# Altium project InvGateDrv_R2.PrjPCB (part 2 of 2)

## Sheet InvGateDriver_4.SchDoc
size A3; SheetNumber: 4; SheetTotal: 7; PageSetup: Record=PageOptions¦CenterHorizontal=True¦CenterVertical=True¦PrintScale=0.69¦XCorrection=1.00¦YCorrection=1.00¦PrintKind=0¦BorderSize=5000000¦LeftOffset=0¦BottomOffset=0¦Orientation=2¦PaperLength=1000¦PaperWidth=1000¦Scale=100¦PaperSource=15¦PrintQuality=600¦MediaType=1¦DitherType=10¦PaperKind=Letter¦PrintScaleMode=1
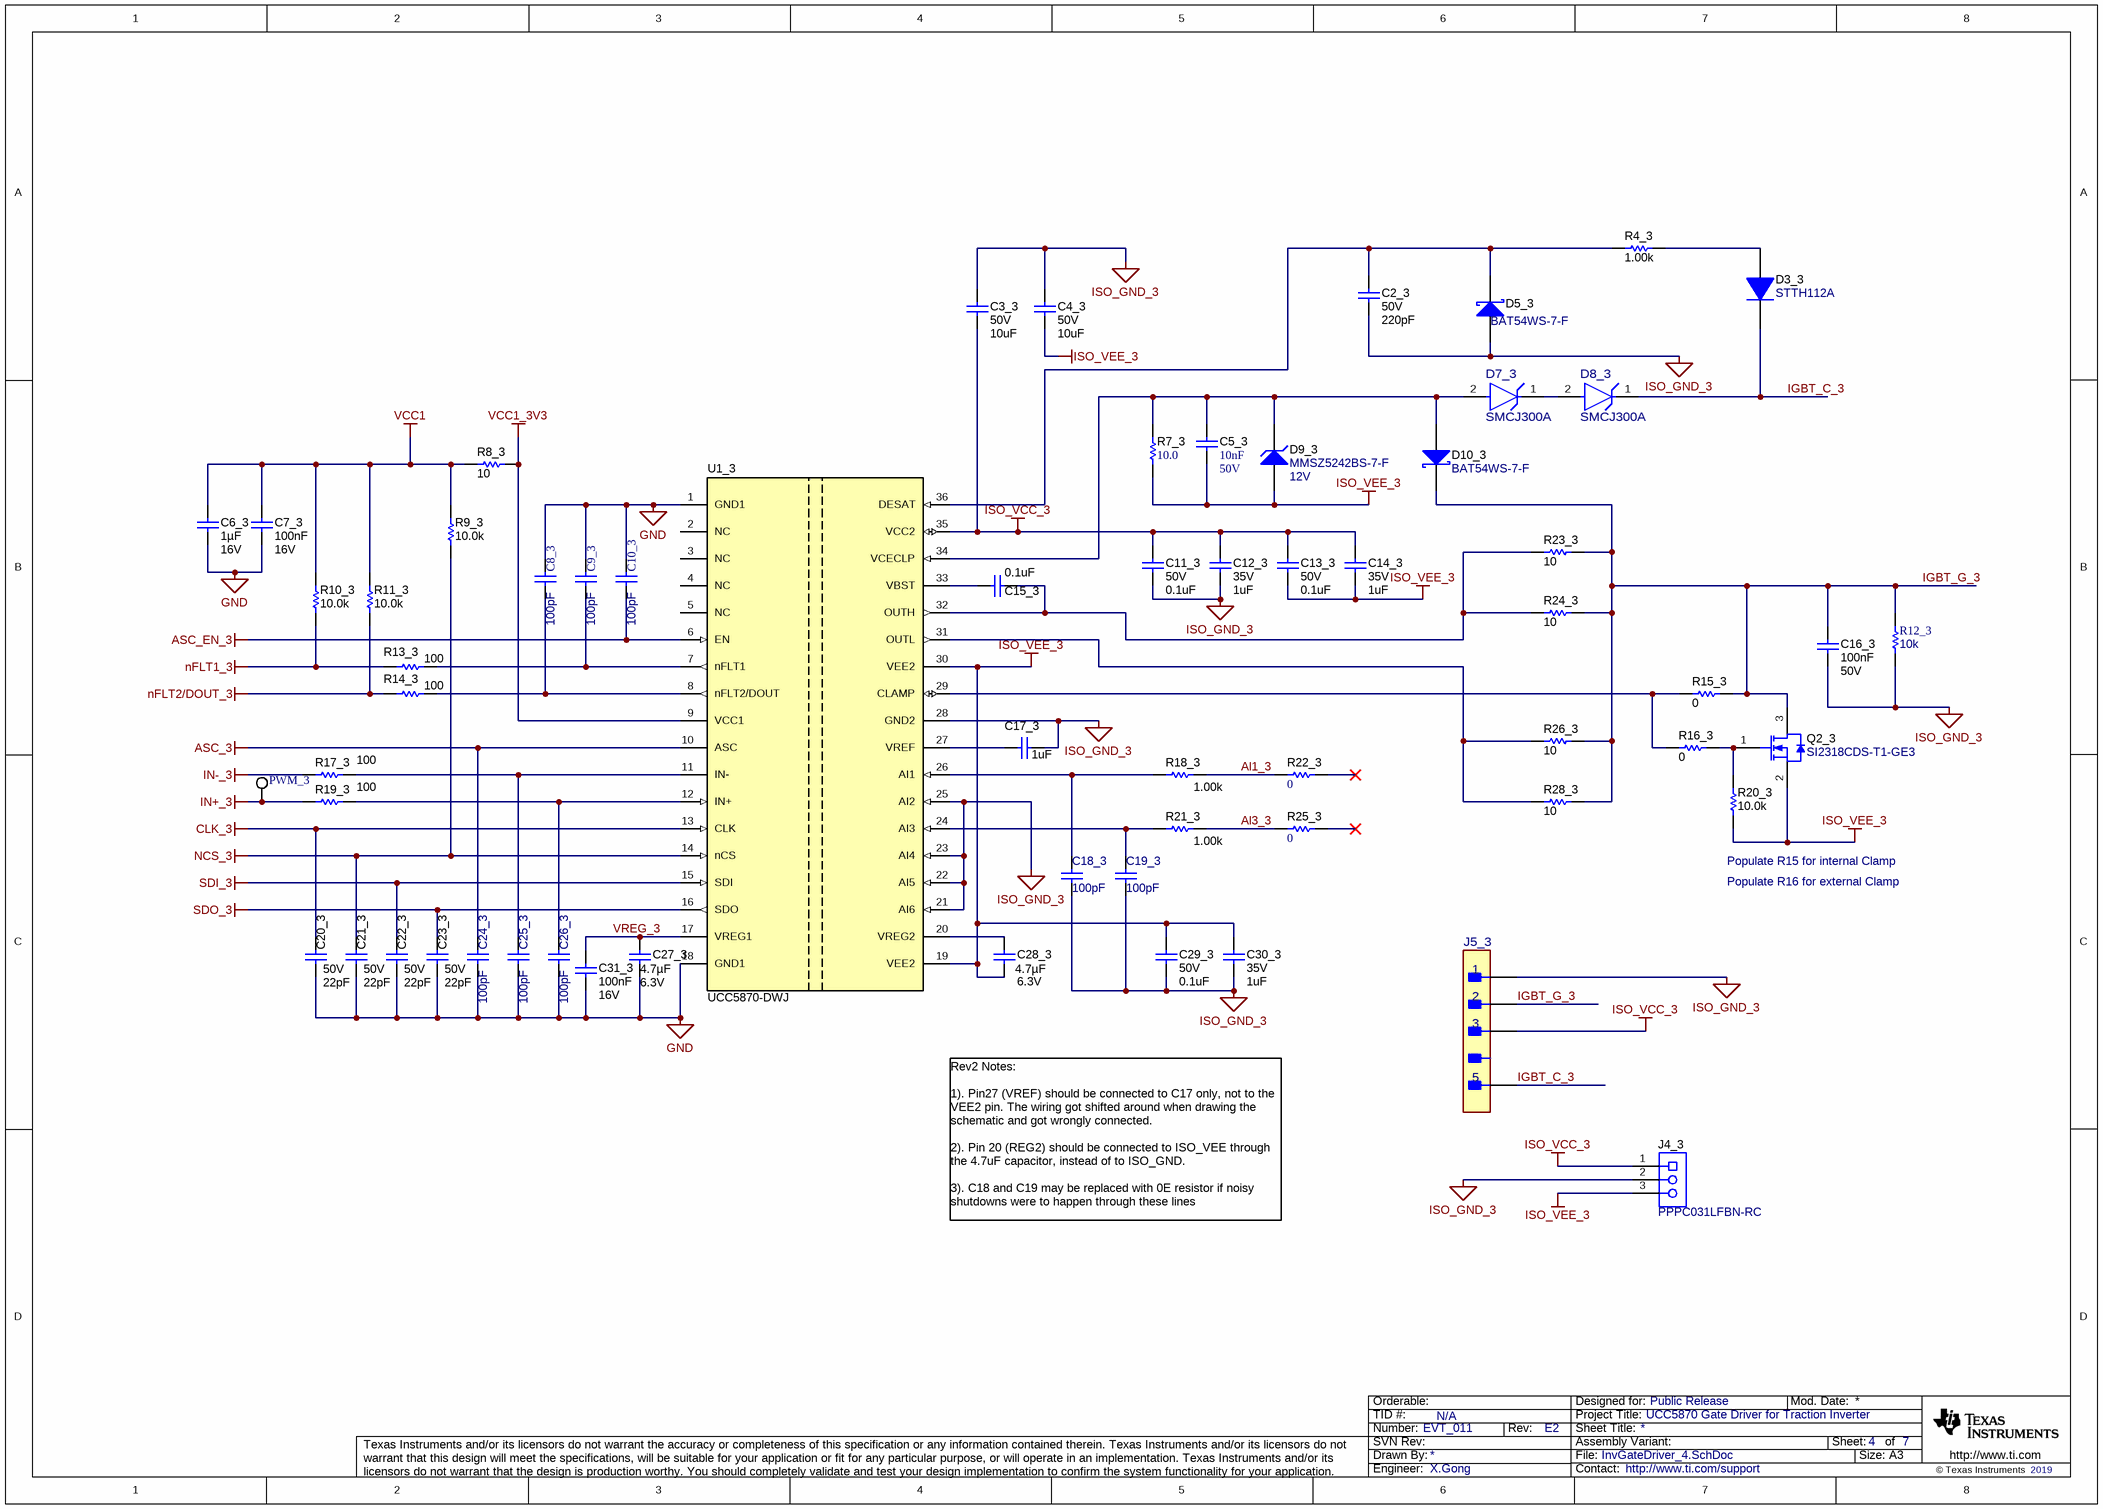
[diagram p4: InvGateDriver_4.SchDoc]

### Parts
C2_3  VDC_V: 50V  ValueDisplayed: 220pF  [0603]  (hidden comment: GRM188R71H221KA01D)
C3_3  VDC_V: 50V  ValueDisplayed: 10uF  [1206_180]  (hidden comment: CL31B106KBHNNNE)
C4_3  VDC_V: 50V  ValueDisplayed: 10uF  [1206_180]  (hidden comment: CL31B106KBHNNNE)
C5_3  Cap_F: 10nF  VDC_V: 50V  [0603]  (hidden comment: GRM188R71H103KA01D)
C6_3  Cap_F: 1µF  VDC_V: 16V  [0603]  (hidden comment: GCM188R71C105MA64D)
C7_3  Cap_F: 100nF  VDC_V: 16V  [0603]  (hidden comment: CGJ3E2X7R1C104K080AA)
C8_3  ValueDisplayed: 100pF  [0603]  (hidden comment: GCM1885C1H101JA16J)
C9_3  ValueDisplayed: 100pF  [0603]  (hidden comment: GCM1885C1H101JA16J)
C10_3  ValueDisplayed: 100pF  [0603]  (hidden comment: GCM1885C1H101JA16J)
C11_3  VDC_V: 50V  ValueDisplayed: 0.1uF  [0603]  (hidden comment: C1608X5R1H104K080AA)
C12_3  VDC_V: 35V  ValueDisplayed: 1uF  [0603]  (hidden comment: CGA3E1X7R1V105K080AC)
C13_3  VDC_V: 50V  ValueDisplayed: 0.1uF  [0603]  (hidden comment: C1608X5R1H104K080AA)
C14_3  VDC_V: 35V  ValueDisplayed: 1uF  [0603]  (hidden comment: CGA3E1X7R1V105K080AC)
C15_3  ValueDisplayed: 0.1uF  [0603]  (hidden comment: C1608X5R1H104K080AA)
C16_3  Cap_F: 100nF  VDC_V: 50V  [0805_HV]  (hidden comment: C0805C104K5RACAUTO)
C17_3  ValueDisplayed: 1uF  [0603]  (hidden comment: CGA3E1X7R1V105K080AC)
C18_3  ValueDisplayed: 100pF  [0603]  (hidden comment: GCM1885C1H101JA16J)
C19_3  ValueDisplayed: 100pF  [0603]  (hidden comment: GCM1885C1H101JA16J)
C20_3  VDC_V: 50V  ValueDisplayed: 22pF  [0603]  (hidden comment: CGA3E2C0G1H220J080AA)
C21_3  VDC_V: 50V  ValueDisplayed: 22pF  [0603]  (hidden comment: CGA3E2C0G1H220J080AA)
C22_3  VDC_V: 50V  ValueDisplayed: 22pF  [0603]  (hidden comment: CGA3E2C0G1H220J080AA)
C23_3  VDC_V: 50V  ValueDisplayed: 22pF  [0603]  (hidden comment: CGA3E2C0G1H220J080AA)
C24_3  ValueDisplayed: 100pF  [0603]  (hidden comment: GCM1885C1H101JA16J)
C25_3  ValueDisplayed: 100pF  [0603]  (hidden comment: GCM1885C1H101JA16J)
C26_3  ValueDisplayed: 100pF  [0603]  (hidden comment: GCM1885C1H101JA16J)
C27_3  Cap_F: 4.7µF  VDC_V: 6.3V  [0603]  (hidden comment: CL10B475KQ8NQND)
C28_3  Cap_F: 4.7µF  VDC_V: 6.3V  [0603]  (hidden comment: CL10B475KQ8NQND)
C29_3  VDC_V: 50V  ValueDisplayed: 0.1uF  [0603]  (hidden comment: C1608X5R1H104K080AA)
C30_3  VDC_V: 35V  ValueDisplayed: 1uF  [0603]  (hidden comment: CGA3E1X7R1V105K080AC)
C31_3  Cap_F: 100nF  VDC_V: 16V  [0603]  (hidden comment: CGJ3E2X7R1C104K080AA)
D3_3  STTH112A  [SMA]
D5_3  BAT54WS-7-F  [SOD-323]
D7_3  SMCJ300A  [FP-SMCJ300A_DO214AB-MFG]
D8_3  SMCJ300A  [FP-SMCJ300A_DO214AB-MFG]
D9_3  MMSZ5242BS-7-F  value 12V  [SOD-323]
D10_3  BAT54WS-7-F  [SOD-323]
J4_3  PPPC031LFBN-RC  [Sullins_PPPC031LFBN-RC]
J5_3  TSW-105-08-G-S-RA-004  [FP-TSW-105-08-G-S-RA-004_HDR4-MFG]  (value not drawn)
PWM_3  5002  [Keystone5002]  (value not drawn)
Q2_3  SI2318CDS-T1-GE3  [SOT-23]
R4_3  ValueDisplayed: 1.00k  [0603]  (hidden comment: CRCW06031K00FKEA)
R7_3  ValueDisplayed: 10.0  [0805_HV]  (hidden comment: CRCW080510R0FKEA)
R8_3  ValueDisplayed: 10  [0805_HV]  (hidden comment: CRCW080510R0JNEA)
R9_3  ValueDisplayed: 10.0k  [0603]  (hidden comment: ERJ-3EKF1002V)
R10_3  ValueDisplayed: 10.0k  [0603]  (hidden comment: ERJ-3EKF1002V)
R11_3  ValueDisplayed: 10.0k  [0603]  (hidden comment: ERJ-3EKF1002V)
R12_3  ValueDisplayed: 10k  [0603]  (hidden comment: CRCW060310K0JNEA)
R13_3  ValueDisplayed: 100  [0603]  (hidden comment: CRCW0603100RJNEA)
R14_3  ValueDisplayed: 100  [0603]  (hidden comment: CRCW0603100RJNEA)
R15_3  ValueDisplayed: 0  [0805_HV]  (hidden comment: CRCW08050000Z0EA)
R16_3  ValueDisplayed: 0  [0805_HV]  (hidden comment: CRCW08050000Z0EA)
R17_3  ValueDisplayed: 100  [0603]  (hidden comment: CRCW0603100RJNEA)
R18_3  ValueDisplayed: 1.00k  [0603]  (hidden comment: CRCW06031K00FKEA)
R19_3  ValueDisplayed: 100  [0603]  (hidden comment: CRCW0603100RJNEA)
R20_3  ValueDisplayed: 10.0k  [0603]  (hidden comment: RCG060310K0FKEA)
R21_3  ValueDisplayed: 1.00k  [0603]  (hidden comment: CRCW06031K00FKEA)
R22_3  ValueDisplayed: 0  [0603]  (hidden comment: CRCW06030000Z0EA)
R23_3  ValueDisplayed: 10  [2010]  (hidden comment: CRCW201010R0JNEF)
R24_3  ValueDisplayed: 10  [2010]  (hidden comment: CRCW201010R0JNEF)
R25_3  ValueDisplayed: 0  [0603]  (hidden comment: CRCW06030000Z0EA)
R26_3  ValueDisplayed: 10  [2010]  (hidden comment: CRCW201010R0JNEF)
R28_3  ValueDisplayed: 10  [2010]  (hidden comment: CRCW201010R0JNEF)
U1_3  UCC5870-DWJ  [DWJ0036A]

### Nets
ASC_3: C24_3.1 U1_3.10(ASC)  [project net ASC_1]
ASC_EN_3: C10_3.2 U1_3.6(EN)  [project net ASC_EN]
CLK_3: C20_3.1 U1_3.13(CLK)  [project net CLK]
GND: C6_3.2 C7_3.2 C8_3.1 C9_3.1 C10_3.1 C20_3.2 C21_3.2 C22_3.2 C23_3.2 C24_3.2 C25_3.2 C26_3.2 C27_3.2 C31_3.2 U1_3.1(GND1) U1_3.18(GND1)
IN+_3: PWM_3.1 R19_3.1  [project net IN+_B]
IN-_3: R17_3.1  [project net IN-_B]
ISO_GND_3: C2_3.1 C3_3.1 C4_3.1 C11_3.2 C12_3.2 C16_3.2 C17_3.2 C18_3.2 C19_3.2 C29_3.2 C30_3.1 D5_3.2(A) J4_3.2 J5_3.1 R12_3.1 U1_3.21(AI6) U1_3.22(AI5) U1_3.23(AI4) U1_3.25(AI2) U1_3.28(GND2)
ISO_VCC_3: C3_3.2 C11_3.1 C12_3.1 C13_3.1 C14_3.1 J4_3.1 J5_3.3 U1_3.35(VCC2)
ISO_VEE_3: C4_3.2 C5_3.2 C13_3.2 C14_3.2 C28_3.2 C29_3.1 C30_3.2 D9_3.2(A) J4_3.3 Q2_3.2(S) R7_3.1 R20_3.1 U1_3.19(VEE2) U1_3.30(VEE2)
NCS_3: C21_3.1 R9_3.1 U1_3.14(nCS)  [project net NCS]
nFLT1_3: R10_3.2 R13_3.1  [project net nFLT1_1]
nFLT2/DOUT_3: R11_3.1 R14_3.1  [project net nFLT2/DOUT_1]
SDI_3: C22_3.1 U1_3.15(SDI)  [project net SDI]
SDO_3: C23_3.1 U1_3.16(SDO)  [project net SDO]
VCC1: C6_3.1 C7_3.1 R8_3.1 R9_3.2 R10_3.1 R11_3.2
VCC1_3V3: R8_3.2 U1_3.9(VCC1)
Al1_3: R18_3.2 R22_3.1
Al3_3: R21_3.2 R25_3.1
IGBT_C_3: D3_3.1(K) D8_3.1(CATHODE) J5_3.5
IGBT_G_3: C16_3.1 D10_3.1(K) J5_3.2 Q2_3.3(D) R12_3.2 R15_3.1 R23_3.2 R24_3.2 R26_3.2 R28_3.2
VREG_3: C27_3.1 C31_3.1 U1_3.17(VREG1)
NetC2_3_2: C2_3.2 D5_3.1(K) R4_3.1 U1_3.36(DESAT)
NetC5_3_1: C5_3.1 D7_3.2(ANODE) D9_3.1(K) D10_3.2(A) R7_3.2 U1_3.34(VCECLP)
NetC8_3_2: C8_3.2 R14_3.2 U1_3.8(nFLT2/DOUT)
NetC9_3_2: C9_3.2 R13_3.2 U1_3.7(nFLT1)
NetC15_3_1: C15_3.1 U1_3.33(VBST)
NetC15_3_2: C15_3.2 R23_3.1 R24_3.1 U1_3.32(OUTH)
NetC17_3_1: C17_3.1 U1_3.27(VREF)
NetC18_3_1: C18_3.1 R18_3.1 U1_3.26(AI1)
NetC19_3_1: C19_3.1 R21_3.1 U1_3.24(AI3)
NetC25_3_1: C25_3.1 R17_3.2 U1_3.11(IN-)
NetC26_3_1: C26_3.1 R19_3.2 U1_3.12(IN+)
NetC28_3_1: C28_3.1 U1_3.20(VREG2)
NetD3_3_2: D3_3.2(A) R4_3.2
NetD7_3_1: D7_3.1(CATHODE) D8_3.2(ANODE)
NetQ2_3_1: Q2_3.1(G) R16_3.1 R20_3.2
NetR15_3_2: R15_3.2 R16_3.2 U1_3.29(CLAMP)
NetR26_3_1: R26_3.1 R28_3.1 U1_3.31(OUTL)

Not connected (* = marked no-connect by the designer): R22_3 2*; R25_3 2*; U1_3 2(NC) 3(NC) 4(NC) 5(NC)

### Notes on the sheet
- (near R20_3) Populate R15 for internal Clamp
- Populate R16 for external Clamp
- Rev2 Notes:
  1). Pin27 (VREF) should be connected to C17 only, not to the VEE2 pin. The wiring got shifted around when drawing the schematic and got wrongly connected.
  2). Pin 20 (REG2) should be connected to ISO_VEE through the 4.7uF capacitor, instead of to ISO_GND.
  3). C18 and C19 may be replaced with 0E resistor if noisy shutdowns were to happen through these lines

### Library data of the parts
C2_3 = CMP-0007442-5: CAP, CERM, 220 pF, 50 V, +/- 10%, X7R, 0603; Manufacturer: MuRata; TaMin_C: -55°C; Polarized: N; SizeAreaWB_mm2: 4.68; Value1: Unknown; U/M: EA; Value: 220pF; TaMax_C: 125°C; SizeZ_mm: 1; SizeX_mm: 1.6; SizeY_mm: 0.8; SizeArea_mm2: 1.28; AEC Category: Q200
C3_3 = CMP-0008802-2: CAP, CERM, 10 uF, 50 V, +/- 10%, X7R, 1206; Manufacturer: Samsung; TaMin_C: -55°C; Polarized: N; SizeAreaWB_mm2: 10.92; Value1: Unknown; U/M: EA; Value: 10uF; TaMax_C: 125°C; SizeZ_mm: 1.8; SizeX_mm: 3.2; SizeY_mm: 1.6; Cap_Case: 1206; SizeArea_mm2: 5.12; Cap_F: 10µF; AEC Category: Q200
C4_3 = CMP-0008802-2: CAP, CERM, 10 uF, 50 V, +/- 10%, X7R, 1206; Manufacturer: Samsung; TaMin_C: -55°C; Polarized: N; SizeAreaWB_mm2: 10.92; Value1: Unknown; U/M: EA; Value: 10uF; TaMax_C: 125°C; SizeZ_mm: 1.8; SizeX_mm: 3.2; SizeY_mm: 1.6; Cap_Case: 1206; SizeArea_mm2: 5.12; CompType: Capacitor; Cap_F: 10µF; AEC Category: Q200
C5_3 = CMP-0007433-4: CAP, CERM, 0.01 uF, 50 V, +/- 10%, X7R, 0603; Manufacturer: MuRata; TaMin_C: -55°C; Polarized: N; SizeAreaWB_mm2: 4.68; Value1: Unknown; U/M: EA; Value: 0.01uF; TaMax_C: 125°C; SizeZ_mm: 1; SizeX_mm: 1.6; SizeY_mm: 0.8; SizeArea_mm2: 1.28; AEC Category: Q200
C6_3 = CMP-0007137-5: CAP, CERM, 1 uF, 16 V, +/- 20%, X7R, AEC-Q200 Grade 1, 0603; Manufacturer: MuRata; TaMin_C: -55°C; Polarized: N; SizeAreaWB_mm2: 4.68; Value1: Unknown; U/M: EA; Value: 1uF; TaMax_C: 125°C; SizeZ_mm: 1; SizeX_mm: 1.6; SizeY_mm: 0.8; SizeArea_mm2: 1.28; AEC Qualified: Y; AEC Category: Q200
C7_3 = CMP-0007106-4: CAP, CERM, 0.1 uF, 16 V, +/- 10%, X7R, AEC-Q200 Grade 1, 0603; Manufacturer: TDK; TaMin_C: -55°C; Polarized: N; SizeAreaWB_mm2: 4.68; Value1: Unknown; U/M: EA; Value: 0.1uF; TaMax_C: 125°C; SizeZ_mm: 1; SizeX_mm: 1.6; SizeY_mm: 0.8; SizeArea_mm2: 1.28; AEC Qualified: Y; AEC Category: Q200
C8_3 C9_3 C10_3 C18_3 C19_3 C24_3 C25_3 C26_3 = CMP-0750041-1: CAP, CERM, 100 pF, 50 V,+/- 5%, C0G/NP0, AEC-Q200 Grade 1, 0603; Manufacturer: MuRata; AEC Grade: 1; SizeArea_mm2: 1.28; SizeX_mm: 1.6; Polarized: N; TaMax_C: 125°C; Value2: 50V; Value: 100pF; U/M: EA; CompType: Capacitor; AEC Qualified: Y; SizeAreaWB_mm2: 4.68; TaMin_C: -55°C; SizeY_mm: 0.8; AEC Category: Q200
C11_3 C29_3 = CMP-0007010-5: CAP, CERM, 0.1 uF, 50 V, +/- 10%, X5R, 0603; Manufacturer: TDK; TaMin_C: -55°C; ESR_ohm: 0.0296; Polarized: N; SizeAreaWB_mm2: 4.68; Value1: 0.0296 ohm; U/M: EA; Value: 0.1uF; TaMax_C: 85°C; SizeZ_mm: 1; SizeX_mm: 1.6; SizeY_mm: 0.8; SizeArea_mm2: 1.28; Cap_F: 100nF; IRMS_A: 9.7199dA; AEC Category: Q200
C12_3 C14_3 C30_3 = CMP-0007067-4: CAP, CERM, 1 uF, 35 V, +/- 10%, X7R, AEC-Q200 Grade 1, 0603; Manufacturer: TDK; TaMin_C: -55°C; ESR_ohm: 5.522m; Polarized: N; SizeAreaWB_mm2: 4.68; Value1: 0.005522 ohm; U/M: EA; Value: 1uF; TaMax_C: 125°C; SizeZ_mm: 1; SizeX_mm: 1.6; SizeY_mm: 0.8; SizeArea_mm2: 1.28; CompType: Capacitor; AEC Qualified: Y; Cap_F: 1µF; IRMS_A: 2.21617A; AEC Category: Q200
C13_3 = CMP-0007010-5: CAP, CERM, 0.1 uF, 50 V, +/- 10%, X5R, 0603; Manufacturer: TDK; TaMin_C: -55°C; ESR_ohm: 0.0296; Polarized: N; SizeAreaWB_mm2: 4.68; Value1: 0.0296 ohm; U/M: EA; Value: 0.1uF; TaMax_C: 85°C; SizeZ_mm: 1; SizeX_mm: 1.6; SizeY_mm: 0.8; SizeArea_mm2: 1.28; CompType: Capacitor; Cap_F: 100nF; IRMS_A: 9.7199dA; AEC Category: Q200
C15_3 = CMP-0007010-5: CAP, CERM, 0.1 uF, 50 V, +/- 10%, X5R, 0603; Manufacturer: TDK; TaMin_C: -55°C; ESR_ohm: 0.0296; Polarized: N; SizeAreaWB_mm2: 4.68; Value1: 0.0296 ohm; U/M: EA; Value: 0.1uF; TaMax_C: 85°C; SizeZ_mm: 1; SizeX_mm: 1.6; SizeY_mm: 0.8; Value2: 50V; SizeArea_mm2: 1.28; CompType: Capacitor; Cap_F: 100nF; IRMS_A: 9.7199dA; AEC Category: Q200
C16_3 = CMP-0007725-2: CAP, CERM, 0.1 uF, 50 V, +/- 10%, X7R, AEC-Q200 Grade 0, 0805; Manufacturer: Kemet; TaMin_C: -55°C; Polarized: N; SizeAreaWB_mm2: 6.75; Value1: Unknown; U/M: EA; Value: 0.1uF; TaMax_C: 125°C; SizeZ_mm: 1.45; SizeX_mm: 2; SizeY_mm: 1.25; Cap_Case: 0805; SizeArea_mm2: 2.5; AEC Qualified: Y; AEC Grade: 0; AEC Category: Q200
C17_3 = CMP-0007067-4: CAP, CERM, 1 uF, 35 V, +/- 10%, X7R, AEC-Q200 Grade 1, 0603; Manufacturer: TDK; TaMin_C: -55°C; ESR_ohm: 5.522m; Polarized: N; SizeAreaWB_mm2: 4.68; Value1: 0.005522 ohm; U/M: EA; Value: 1uF; TaMax_C: 125°C; SizeZ_mm: 1; SizeX_mm: 1.6; SizeY_mm: 0.8; Value2: 35V; SizeArea_mm2: 1.28; CompType: Capacitor; AEC Qualified: Y; Cap_F: 1µF; IRMS_A: 2.21617A; AEC Category: Q200
C20_3 C21_3 C22_3 C23_3 = CMP-0007071-3: CAP, CERM, 22 pF, 50 V, +/- 5%, C0G/NP0, AEC-Q200 Grade 1, 0603; Manufacturer: TDK; TaMin_C: -55°C; Polarized: N; SizeAreaWB_mm2: 4.68; Value1: Unknown; U/M: EA; Value: 22pF; TaMax_C: 125°C; SizeZ_mm: 1; SizeX_mm: 1.6; SizeY_mm: 0.8; SizeArea_mm2: 1.28; AEC Qualified: Y; AEC Category: Q200
C27_3 C28_3 = CMP-0007112-4: CAP, CERM, 4.7 uF, 6.3 V, +/- 10%, X7R, 0603; Manufacturer: Samsung; TaMin_C: -55°C; Polarized: N; SizeAreaWB_mm2: 4.68; Value1: Unknown; U/M: EA; Value: 4.7uF; TaMax_C: 125°C; SizeZ_mm: 1; SizeX_mm: 1.6; SizeY_mm: 0.8; SizeArea_mm2: 1.28; CompType: Capacitor; AEC Category: Q200
C31_3 = CMP-0007106-4: CAP, CERM, 0.1 uF, 16 V, +/- 10%, X7R, AEC-Q200 Grade 1, 0603; Manufacturer: TDK; TaMin_C: -55°C; Polarized: N; SizeAreaWB_mm2: 4.68; Value1: Unknown; U/M: EA; Value: 0.1uF; TaMax_C: 125°C; SizeZ_mm: 1; SizeX_mm: 1.6; SizeY_mm: 0.8; SizeArea_mm2: 1.28; CompType: Capacitor; AEC Qualified: Y; AEC Category: Q200
D3_3 = CMP-0077081-2: Diode, Ultrafast, 1200 V, 1 A, SMA; Manufacturer: STMicroelectronics; SizeAreaWB_mm2: 37.3428; Vr_V: 1.2kV; SizeArea_mm2: 16.3228; AEC Qualified: N; TJmax_C: 175°C; AEC Category: Q101; Value: 1200V; SizeZ_mm: 2.87; Green_REACh: Incomplete; Io_A: 1A; Vf_V: 1.9V; SizeY_mm: 2.92; Green_Lifecycle: Not Set; SizeX_mm: 5.59
D5_3 D10_3 = CMP-0028458-2: Diode, Schottky, 30 V, 0.2 A, SOD-323; Manufacturer: Diodes Inc.; Io_A: 200mA; Green_Lifecycle: Active; SizeAreaWB_mm2: 8.695; Vr_V: 30V; Green_REACh: Passed; Value1: 0.2A; TJmax_C: 125°C; Value: 30V; SizeZ_mm: 1; SizeX_mm: 2.7; SizeY_mm: 1.35; Vf_V: 700mV; Value2: 0.7V; SizeArea_mm2: 3.645; AEC Category: Q101
D7_3 D8_3 = CMP-0088475-1: 486V Clamp 3.1A Ipp Tvs Diode Surface Mount DO-214AB (SMCJ); Manufacturer: Littelfuse Inc; Ppk: 1.5kW; VRWM: 300V; AEC Qualified: No; TJmax_C: +150°C; Number Of Channels: 1; Direction: Unidirectional; SizeZ_mm: 2.62mm; Breakdown Voltage: 335V
D9_3 = CMP-0005831-4: Diode, Zener, 12 V, 200 mW, SOD-323; Manufacturer: Diodes Inc.; Power_W: 200mW; SizeAreaWB_mm2: 8.695; Value1: 0.2W; RJA_CperW: 350; SizeZ_mm: 1; SizeX_mm: 2.7; SizeY_mm: 1.35; SizeArea_mm2: 3.645; AEC Category: Q101
J4_3 = CMP-0054646-1: Receptacle, 100mil, 3x1, Gold, TH; Manufacturer: Sullins Connector Solutions; CT: TRUE; CompType: Socket Strip; CNHeader: FALSE
J5_3 = CMP-0088430-1: THROUGH-HOLE .025" SQ POST HEADER; Manufacturer: Samtec; SizeZ_mm: 3.15mm; Row_Count: 1; Voltage_V: 550V; ContactFinish: Gold,Nickel; Conn Orientation: Right Angle; Conn Gender: Male; AEC Qualified: No; DUT-Pitch_mm: 2.54mm
PWM_3 = CMP-0055139-1: Test Point, Miniature, White, TH; Manufacturer: Keystone; ContactFinish: Silver; Green_Lifecycle: Active; Green_REACh: Passed; CNHeader: FALSE; CT: TRUE
Q2_3 = CMP-0000739-1: MOSFET, N-CH, 40 V, 5.6 A, SOT-23; Alternate Manufacturer: None; Manufacturer: Vishay-Siliconix; SizeZ_mm: 1.1; ChType: N; Value2: 5.8 nC; Value1: 0.05; VdsMax_V: 40V; SizeX_mm: 2.5; SizeY_mm: 3; Vgs_V: 20V; Value: 40V; Rdson45_ohm: 0.051; SizeArea_mm2: 7.5; AEC Category: Q101; IdsMax_A: 5.6A; SizeAreaWB_mm2: 14; U/M: EA; QgTyp_nC: 5.8
R4_3 R18_3 R21_3 = CMP-0022109-5: RES, 1.00 k, 1%, 0.1 W, AEC-Q200 Grade 0, 0603; Manufacturer: Vishay-Dale; Power_W: 100mW; TempCo: 100 ppm/C; Value_Code: 1k00; Value: 1.00k; EIA_Code: E96; Res_ohm: 1k; SizeX_mm: 1.6; SizeY_mm: 0.8; SizeZ_mm: 1; Value2: 0.1W; SizeArea_mm2: 1.28; AEC Qualified: Y; VDC_V: 75V; AEC Category: Q200; AEC Grade: 0
R7_3 = CMP-0020847-3: RES, 10.0, 1%, 0.125 W, AEC-Q200 Grade 0, 0805; Manufacturer: Vishay-Dale; Power_W: 125mW; TempCo: 100 ppm/C; Value_Code: 10R0; Value: 10.0; EIA_Code: E96; Res_ohm: 10; SizeX_mm: 2; SizeY_mm: 1.25; SizeZ_mm: 1.45; Value2: 0.125W; SizeArea_mm2: 2.5; AEC Qualified: Y; VDC_V: 150V; AEC Category: Q200; AEC Grade: 0
R8_3 = CRCW080510R0JNEA: RES, 10, 5%, 0.125 W, 0805; Manufacturer: Vishay-Dale; CompType: Resistor; Value: 10; Value_Code: 10R0; Tolerance_%: 5; Power_W: 0.125; Value2: 0.125W; VDC_V: 150; TempCo: 200 ppm/C; SizeArea_mm2: 2.5; SizeX_mm: 2; SizeY_mm: 1.25; SizeZ_mm: 1.45; EIA_Code: E24; U/M: EA; AEC Category: Q200; Green_Lifecycle: Active; Green_REACh: Passed
R9_3 R10_3 R11_3 = CMP-0022684-3: RES, 10.0 k, 1%, 0.1 W, 0603; Manufacturer: Panasonic; Power_W: 100mW; TempCo: 100 ppm/C; Value_Code: 10k0; U/M: EA; Value: 10.0k; EIA_Code: E96; Res_ohm: 10k; SizeX_mm: 1.6; SizeY_mm: 0.8; SizeZ_mm: 1; Value2: 0.1W; SizeArea_mm2: 1.28; VDC_V: 75V; AEC Category: Q200
R12_3 = CMP-0025701-4: RES, 10 k, 5%, 0.1 W, AEC-Q200 Grade 0, 0603; Manufacturer: Vishay-Dale; Power_W: 100mW; TempCo: 200 ppm/C; Value_Code: 10k0; Value: 10k; EIA_Code: E24; SizeX_mm: 1.6; SizeY_mm: 0.8; SizeZ_mm: 1; Value2: 0.1W; SizeArea_mm2: 1.28; AEC Qualified: Y; VDC_V: 75V; AEC Category: Q200; AEC Grade: 0
R13_3 R14_3 R17_3 R19_3 = CMP-0025700-4: RES, 100, 5%, 0.1 W, AEC-Q200 Grade 0, 0603; Manufacturer: Vishay-Dale; Power_W: 100mW; TempCo: 200 ppm/C; Value_Code: 100R; Value: 100; EIA_Code: E24; SizeX_mm: 1.6; SizeY_mm: 0.8; SizeZ_mm: 1; Value2: 0.1W; SizeArea_mm2: 1.28; AEC Qualified: Y; VDC_V: 75V; AEC Category: Q200; AEC Grade: 0
R15_3 R16_3 = CRCW08050000Z0EA: RES, 0, 5%, 0.125 W, 0805; Manufacturer: Vishay-Dale; CompType: Resistor; Value: 0; Value_Code: 0000; Tolerance_%: 5; Power_W: 0.125; Value2: 0.125W; VDC_V: 150; TempCo: 200 ppm/C; SizeArea_mm2: 2.5; SizeX_mm: 2; SizeY_mm: 1.25; SizeZ_mm: 1.45; EIA_Code: E24; U/M: EA; AEC Category: Q200; Green_Lifecycle: Active; Green_REACh: Passed
R20_3 = RCG060310K0FKEA: RES, 10.0 k, 1%, 0.1 W, 0603; Manufacturer: Vishay Draloric; CompType: Resistor; Value: 10.0k; Res_ohm: 10000; Value_Code: 10k0; Tolerance_%: 1; Power_W: 0.1; Value2: 0.1W; VDC_V: 75; TempCo: 100 ppm/C; SizeArea_mm2: 1.28; SizeX_mm: 1.6; SizeY_mm: 0.8; EIA_Code: E96; U/M: EA; AEC Category: Q200; AEC Qualified: N
R22_3 R25_3 = CMP-0025697-4: RES, 0, 5%, 0.1 W, AEC-Q200 Grade 0, 0603; Manufacturer: Vishay-Dale; Power_W: 100mW; TempCo: 200 ppm/C; Value_Code: 0000; Value: 0; EIA_Code: E24; SizeX_mm: 1.6; SizeY_mm: 0.8; SizeZ_mm: 1; Value2: 0.1W; SizeArea_mm2: 1.28; AEC Qualified: Y; VDC_V: 75V; AEC Category: Q200
R23_3 R24_3 R26_3 R28_3 = CRCW201010R0JNEF: RES, 10, 5%, 0.75 W, AEC-Q200 Grade 0, 2010; Manufacturer: Vishay-Dale; CompType: Resistor; Value: 10; Value_Code: 10R0; Tolerance_%: 5; Power_W: 0.75; Value2: 0.75W; VDC_V: 400; TempCo: 200 ppm/C; SizeArea_mm2: 12.5; SizeY_mm: 2.5; SizeZ_mm: 1.66; EIA_Code: E24; U/M: EA; AEC Category: Q200; AEC Qualified: Y; AEC Grade: 0
U1_3 = CMP-0080759-3: Isolated IGBT, SiC MOSFET Gate Driver With Real-Time Programmability, DWJ0036A (SOIC-36); Alternate Manufacturer: Texas Instruments; SizeAreaWB_mm2: 182.04; SizeZ_mm: 3.55; SizeX_mm: 10.3; SizeY_mm: 12.8; SizeArea_mm2: 131.84; CompType: IC; AEC Qualified: N; AEC Category: Q200

## Sheet InvGateDriver_5.SchDoc
size A3; SheetNumber: 5; SheetTotal: 7; PageSetup: Record=PageOptions¦CenterHorizontal=True¦CenterVertical=True¦PrintScale=0.69¦XCorrection=1.00¦YCorrection=1.00¦PrintKind=0¦BorderSize=5000000¦LeftOffset=0¦BottomOffset=0¦Orientation=2¦PaperLength=1000¦PaperWidth=1000¦Scale=100¦PaperSource=15¦PrintQuality=600¦MediaType=1¦DitherType=10¦PaperKind=Letter¦PrintScaleMode=1
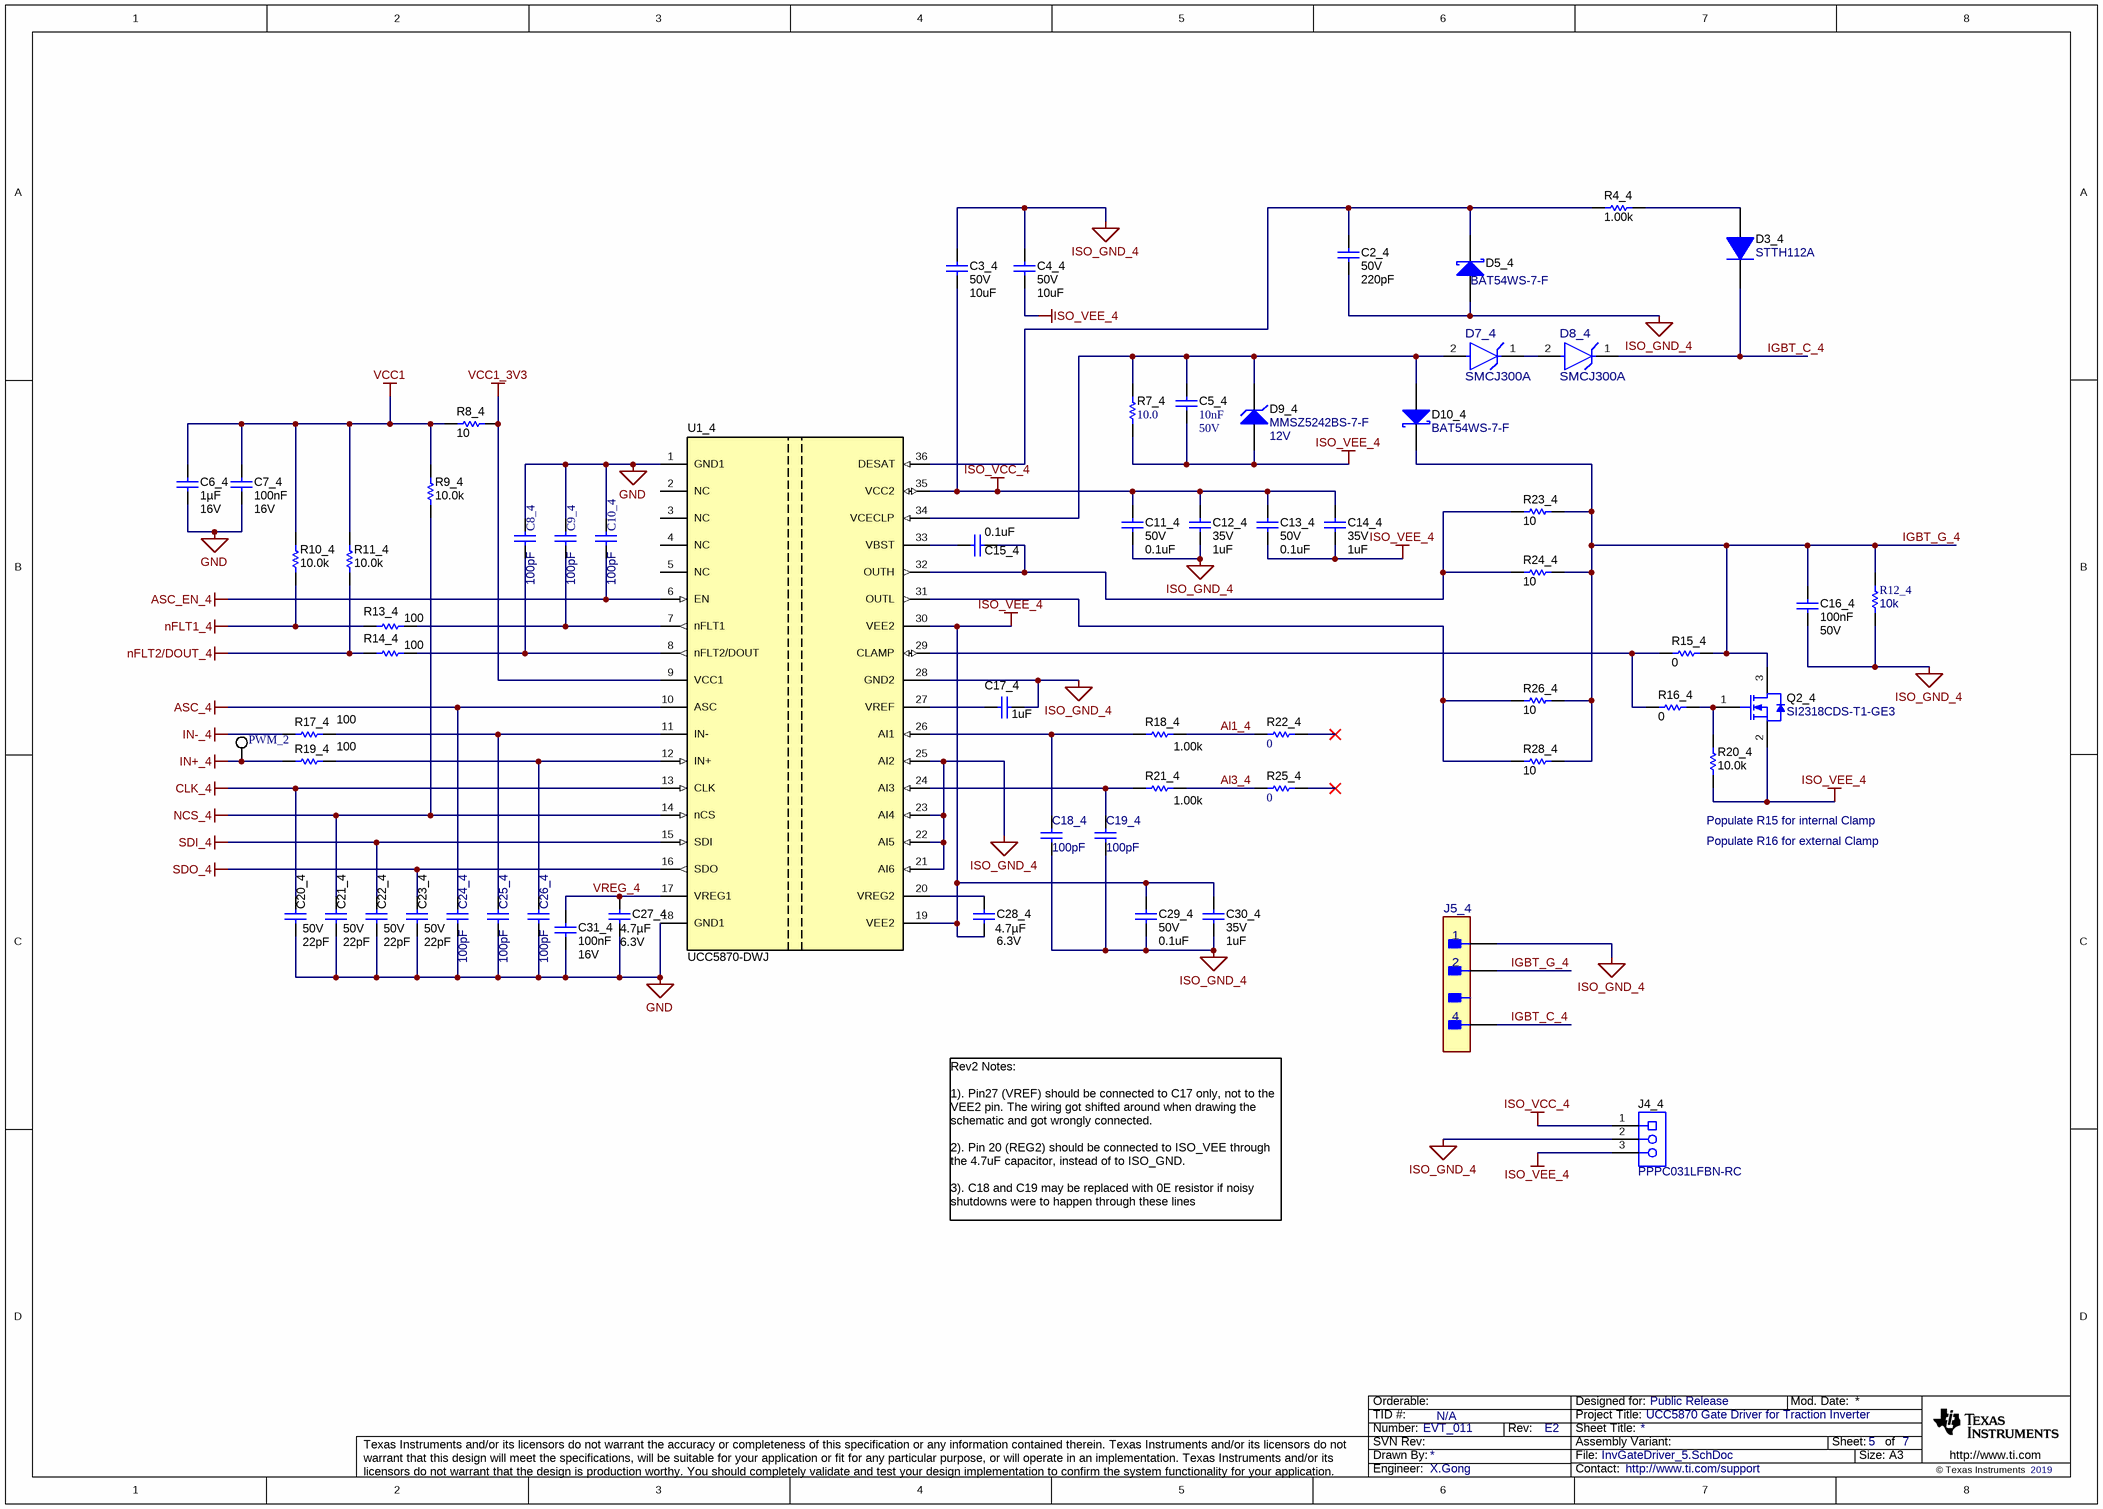
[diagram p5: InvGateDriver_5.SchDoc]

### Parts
C2_4  VDC_V: 50V  ValueDisplayed: 220pF  [0603]  (hidden comment: GRM188R71H221KA01D)
C3_4  VDC_V: 50V  ValueDisplayed: 10uF  [1206_180]  (hidden comment: CL31B106KBHNNNE)
C4_4  VDC_V: 50V  ValueDisplayed: 10uF  [1206_180]  (hidden comment: CL31B106KBHNNNE)
C5_4  Cap_F: 10nF  VDC_V: 50V  [0603]  (hidden comment: GRM188R71H103KA01D)
C6_4  Cap_F: 1µF  VDC_V: 16V  [0603]  (hidden comment: GCM188R71C105MA64D)
C7_4  Cap_F: 100nF  VDC_V: 16V  [0603]  (hidden comment: CGJ3E2X7R1C104K080AA)
C8_4  ValueDisplayed: 100pF  [0603]  (hidden comment: GCM1885C1H101JA16J)
C9_4  ValueDisplayed: 100pF  [0603]  (hidden comment: GCM1885C1H101JA16J)
C10_4  ValueDisplayed: 100pF  [0603]  (hidden comment: GCM1885C1H101JA16J)
C11_4  VDC_V: 50V  ValueDisplayed: 0.1uF  [0603]  (hidden comment: C1608X5R1H104K080AA)
C12_4  VDC_V: 35V  ValueDisplayed: 1uF  [0603]  (hidden comment: CGA3E1X7R1V105K080AC)
C13_4  VDC_V: 50V  ValueDisplayed: 0.1uF  [0603]  (hidden comment: C1608X5R1H104K080AA)
C14_4  VDC_V: 35V  ValueDisplayed: 1uF  [0603]  (hidden comment: CGA3E1X7R1V105K080AC)
C15_4  ValueDisplayed: 0.1uF  [0603]  (hidden comment: C1608X5R1H104K080AA)
C16_4  Cap_F: 100nF  VDC_V: 50V  [0805_HV]  (hidden comment: C0805C104K5RACAUTO)
C17_4  ValueDisplayed: 1uF  [0603]  (hidden comment: CGA3E1X7R1V105K080AC)
C18_4  ValueDisplayed: 100pF  [0603]  (hidden comment: GCM1885C1H101JA16J)
C19_4  ValueDisplayed: 100pF  [0603]  (hidden comment: GCM1885C1H101JA16J)
C20_4  VDC_V: 50V  ValueDisplayed: 22pF  [0603]  (hidden comment: CGA3E2C0G1H220J080AA)
C21_4  VDC_V: 50V  ValueDisplayed: 22pF  [0603]  (hidden comment: CGA3E2C0G1H220J080AA)
C22_4  VDC_V: 50V  ValueDisplayed: 22pF  [0603]  (hidden comment: CGA3E2C0G1H220J080AA)
C23_4  VDC_V: 50V  ValueDisplayed: 22pF  [0603]  (hidden comment: CGA3E2C0G1H220J080AA)
C24_4  ValueDisplayed: 100pF  [0603]  (hidden comment: GCM1885C1H101JA16J)
C25_4  ValueDisplayed: 100pF  [0603]  (hidden comment: GCM1885C1H101JA16J)
C26_4  ValueDisplayed: 100pF  [0603]  (hidden comment: GCM1885C1H101JA16J)
C27_4  Cap_F: 4.7µF  VDC_V: 6.3V  [0603]  (hidden comment: CL10B475KQ8NQND)
C28_4  Cap_F: 4.7µF  VDC_V: 6.3V  [0603]  (hidden comment: CL10B475KQ8NQND)
C29_4  VDC_V: 50V  ValueDisplayed: 0.1uF  [0603]  (hidden comment: C1608X5R1H104K080AA)
C30_4  VDC_V: 35V  ValueDisplayed: 1uF  [0603]  (hidden comment: CGA3E1X7R1V105K080AC)
C31_4  Cap_F: 100nF  VDC_V: 16V  [0603]  (hidden comment: CGJ3E2X7R1C104K080AA)
D3_4  STTH112A  [SMA]
D5_4  BAT54WS-7-F  [SOD-323]
D7_4  SMCJ300A  [FP-SMCJ300A_DO214AB-MFG]
D8_4  SMCJ300A  [FP-SMCJ300A_DO214AB-MFG]
D9_4  MMSZ5242BS-7-F  value 12V  [SOD-323]
D10_4  BAT54WS-7-F  [SOD-323]
J4_4  PPPC031LFBN-RC  [Sullins_PPPC031LFBN-RC]
J5_4  TSW-104-08-G-S-RA-003  [FP-TSW-104-08-G-S-RA-003_HDR3-MFG]  (value not drawn)
PWM_2  5002  [Keystone5002]  (value not drawn)
Q2_4  SI2318CDS-T1-GE3  [SOT-23]
R4_4  ValueDisplayed: 1.00k  [0603]  (hidden comment: CRCW06031K00FKEA)
R7_4  ValueDisplayed: 10.0  [0805_HV]  (hidden comment: CRCW080510R0FKEA)
R8_4  ValueDisplayed: 10  [0805_HV]  (hidden comment: CRCW080510R0JNEA)
R9_4  ValueDisplayed: 10.0k  [0603]  (hidden comment: ERJ-3EKF1002V)
R10_4  ValueDisplayed: 10.0k  [0603]  (hidden comment: ERJ-3EKF1002V)
R11_4  ValueDisplayed: 10.0k  [0603]  (hidden comment: ERJ-3EKF1002V)
R12_4  ValueDisplayed: 10k  [0603]  (hidden comment: CRCW060310K0JNEA)
R13_4  ValueDisplayed: 100  [0603]  (hidden comment: CRCW0603100RJNEA)
R14_4  ValueDisplayed: 100  [0603]  (hidden comment: CRCW0603100RJNEA)
R15_4  ValueDisplayed: 0  [0805_HV]  (hidden comment: CRCW08050000Z0EA)
R16_4  ValueDisplayed: 0  [0805_HV]  (hidden comment: CRCW08050000Z0EA)
R17_4  ValueDisplayed: 100  [0603]  (hidden comment: CRCW0603100RJNEA)
R18_4  ValueDisplayed: 1.00k  [0603]  (hidden comment: CRCW06031K00FKEA)
R19_4  ValueDisplayed: 100  [0603]  (hidden comment: CRCW0603100RJNEA)
R20_4  ValueDisplayed: 10.0k  [0603]  (hidden comment: RCG060310K0FKEA)
R21_4  ValueDisplayed: 1.00k  [0603]  (hidden comment: CRCW06031K00FKEA)
R22_4  ValueDisplayed: 0  [0603]  (hidden comment: CRCW06030000Z0EA)
R23_4  ValueDisplayed: 10  [2010]  (hidden comment: CRCW201010R0JNEF)
R24_4  ValueDisplayed: 10  [2010]  (hidden comment: CRCW201010R0JNEF)
R25_4  ValueDisplayed: 0  [0603]  (hidden comment: CRCW06030000Z0EA)
R26_4  ValueDisplayed: 10  [2010]  (hidden comment: CRCW201010R0JNEF)
R28_4  ValueDisplayed: 10  [2010]  (hidden comment: CRCW201010R0JNEF)
U1_4  UCC5870-DWJ  [DWJ0036A]

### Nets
ASC_4: C24_4.1 U1_4.10(ASC)  [project net ASC]
ASC_EN_4: C10_4.2 U1_4.6(EN)  [project net ASC_EN]
CLK_4: C20_4.1 U1_4.13(CLK)  [project net CLK]
GND: C6_4.2 C7_4.2 C8_4.1 C9_4.1 C10_4.1 C20_4.2 C21_4.2 C22_4.2 C23_4.2 C24_4.2 C25_4.2 C26_4.2 C27_4.2 C31_4.2 U1_4.1(GND1) U1_4.18(GND1)
IN+_4: PWM_2.1 R19_4.1  [project net IN-_A]
IN-_4: R17_4.1  [project net IN+_A]
ISO_GND_4: C2_4.1 C3_4.1 C4_4.1 C11_4.2 C12_4.2 C16_4.2 C17_4.2 C18_4.2 C19_4.2 C29_4.2 C30_4.1 D5_4.2(A) J4_4.2 J5_4.1 R12_4.1 U1_4.21(AI6) U1_4.22(AI5) U1_4.23(AI4) U1_4.25(AI2) U1_4.28(GND2)
ISO_VCC_4: C3_4.2 C11_4.1 C12_4.1 C13_4.1 C14_4.1 J4_4.1 U1_4.35(VCC2)
ISO_VEE_4: C4_4.2 C5_4.2 C13_4.2 C14_4.2 C28_4.2 C29_4.1 C30_4.2 D9_4.2(A) J4_4.3 Q2_4.2(S) R7_4.1 R20_4.1 U1_4.19(VEE2) U1_4.30(VEE2)
NCS_4: C21_4.1 R9_4.1 U1_4.14(nCS)  [project net NCS]
nFLT1_4: R10_4.2 R13_4.1  [project net nFLT1]
nFLT2/DOUT_4: R11_4.1 R14_4.1  [project net nFLT2/DOUT]
SDI_4: C22_4.1 U1_4.15(SDI)  [project net SDI]
SDO_4: C23_4.1 U1_4.16(SDO)  [project net SDO]
VCC1: C6_4.1 C7_4.1 R8_4.1 R9_4.2 R10_4.1 R11_4.2
VCC1_3V3: R8_4.2 U1_4.9(VCC1)
Al1_4: R18_4.2 R22_4.1
Al3_4: R21_4.2 R25_4.1
IGBT_C_4: D3_4.1(K) D8_4.1(CATHODE) J5_4.4
IGBT_G_4: C16_4.1 D10_4.1(K) J5_4.2 Q2_4.3(D) R12_4.2 R15_4.1 R23_4.2 R24_4.2 R26_4.2 R28_4.2
VREG_4: C27_4.1 C31_4.1 U1_4.17(VREG1)
NetC2_4_2: C2_4.2 D5_4.1(K) R4_4.1 U1_4.36(DESAT)
NetC5_4_1: C5_4.1 D7_4.2(ANODE) D9_4.1(K) D10_4.2(A) R7_4.2 U1_4.34(VCECLP)
NetC8_4_2: C8_4.2 R14_4.2 U1_4.8(nFLT2/DOUT)
NetC9_4_2: C9_4.2 R13_4.2 U1_4.7(nFLT1)
NetC15_4_1: C15_4.1 U1_4.33(VBST)
NetC15_4_2: C15_4.2 R23_4.1 R24_4.1 U1_4.32(OUTH)
NetC17_4_1: C17_4.1 U1_4.27(VREF)
NetC18_4_1: C18_4.1 R18_4.1 U1_4.26(AI1)
NetC19_4_1: C19_4.1 R21_4.1 U1_4.24(AI3)
NetC25_4_1: C25_4.1 R17_4.2 U1_4.11(IN-)
NetC26_4_1: C26_4.1 R19_4.2 U1_4.12(IN+)
NetC28_4_1: C28_4.1 U1_4.20(VREG2)
NetD3_4_2: D3_4.2(A) R4_4.2
NetD7_4_1: D7_4.1(CATHODE) D8_4.2(ANODE)
NetQ2_4_1: Q2_4.1(G) R16_4.1 R20_4.2
NetR15_4_2: R15_4.2 R16_4.2 U1_4.29(CLAMP)
NetR26_4_1: R26_4.1 R28_4.1 U1_4.31(OUTL)

Not connected (* = marked no-connect by the designer): R22_4 2*; R25_4 2*; U1_4 2(NC) 3(NC) 4(NC) 5(NC)

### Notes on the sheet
- (near R20_4) Populate R15 for internal Clamp
- Populate R16 for external Clamp
- Rev2 Notes:
  1). Pin27 (VREF) should be connected to C17 only, not to the VEE2 pin. The wiring got shifted around when drawing the schematic and got wrongly connected.
  2). Pin 20 (REG2) should be connected to ISO_VEE through the 4.7uF capacitor, instead of to ISO_GND.
  3). C18 and C19 may be replaced with 0E resistor if noisy shutdowns were to happen through these lines

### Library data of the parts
C2_4 = CMP-0007442-5: as C2_3 on sheet InvGateDriver_4
C3_4 = CMP-0008802-2: as C3_3 on sheet InvGateDriver_4
C4_4 = CMP-0008802-2: as C4_3 on sheet InvGateDriver_4
C5_4 = CMP-0007433-4: as C5_3 on sheet InvGateDriver_4
C6_4 = CMP-0007137-5: as C6_3 on sheet InvGateDriver_4
C7_4 = CMP-0007106-4: as C7_3 on sheet InvGateDriver_4
C8_4 C9_4 C10_4 C18_4 C19_4 C24_4 C25_4 C26_4 = CMP-0750041-1: as C8_3 on sheet InvGateDriver_4
C11_4 C29_4 = CMP-0007010-5: as C11_3 on sheet InvGateDriver_4
C12_4 C14_4 C30_4 = CMP-0007067-4: as C12_3 on sheet InvGateDriver_4
C13_4 = CMP-0007010-5: as C13_3 on sheet InvGateDriver_4
C15_4 = CMP-0007010-5: as C15_3 on sheet InvGateDriver_4
C16_4 = CMP-0007725-2: as C16_3 on sheet InvGateDriver_4
C17_4 = CMP-0007067-4: as C17_3 on sheet InvGateDriver_4
C20_4 C21_4 C22_4 C23_4 = CMP-0007071-3: as C20_3 on sheet InvGateDriver_4
C27_4 C28_4 = CMP-0007112-4: as C27_3 on sheet InvGateDriver_4
C31_4 = CMP-0007106-4: as C31_3 on sheet InvGateDriver_4
D3_4 = CMP-0077081-2: as D3_3 on sheet InvGateDriver_4
D5_4 D10_4 = CMP-0028458-2: as D5_3 on sheet InvGateDriver_4
D7_4 D8_4 = CMP-0088475-1: as D7_3 on sheet InvGateDriver_4
D9_4 = CMP-0005831-4: as D9_3 on sheet InvGateDriver_4
J4_4 = CMP-0054646-1: as J4_3 on sheet InvGateDriver_4
J5_4 = CMP-0088429-1: Conn Unshrouded Header HDR 4 POS 2.54mm Solder RA Thru-Hole Automotive Bulk; Manufacturer: Samtec; Conn Orientation: Right Angle; SizeZ_mm: 3.15mm; Voltage_V: 550V; Row_Count: 1; AEC Qualified: No; ContactFinish: Gold,Nickel; Conn Gender: Male
PWM_2 = CMP-0055139-1: as PWM_3 on sheet InvGateDriver_4
Q2_4 = CMP-0000739-1: as Q2_3 on sheet InvGateDriver_4
R4_4 R18_4 R21_4 = CMP-0022109-5: as R4_3 on sheet InvGateDriver_4
R7_4 = CMP-0020847-3: as R7_3 on sheet InvGateDriver_4
R8_4 = CRCW080510R0JNEA: as R8_3 on sheet InvGateDriver_4
R9_4 R10_4 R11_4 = CMP-0022684-3: as R9_3 on sheet InvGateDriver_4
R12_4 = CMP-0025701-4: as R12_3 on sheet InvGateDriver_4
R13_4 R14_4 R17_4 R19_4 = CMP-0025700-4: as R13_3 on sheet InvGateDriver_4
R15_4 R16_4 = CRCW08050000Z0EA: as R15_3 on sheet InvGateDriver_4
R20_4 = RCG060310K0FKEA: as R20_3 on sheet InvGateDriver_4
R22_4 R25_4 = CMP-0025697-4: as R22_3 on sheet InvGateDriver_4
R23_4 R24_4 R26_4 R28_4 = CRCW201010R0JNEF: as R23_3 on sheet InvGateDriver_4
U1_4 = CMP-0080759-3: as U1_3 on sheet InvGateDriver_4

## Sheet InvGateDriver_6.SchDoc
size A3; SheetNumber: 6; SheetTotal: 7; PageSetup: Record=PageOptions¦CenterHorizontal=True¦CenterVertical=True¦PrintScale=0.69¦XCorrection=1.00¦YCorrection=1.00¦PrintKind=0¦BorderSize=5000000¦LeftOffset=0¦BottomOffset=0¦Orientation=2¦PaperLength=1000¦PaperWidth=1000¦Scale=100¦PaperSource=15¦PrintQuality=600¦MediaType=1¦DitherType=10¦PaperKind=Letter¦PrintScaleMode=1
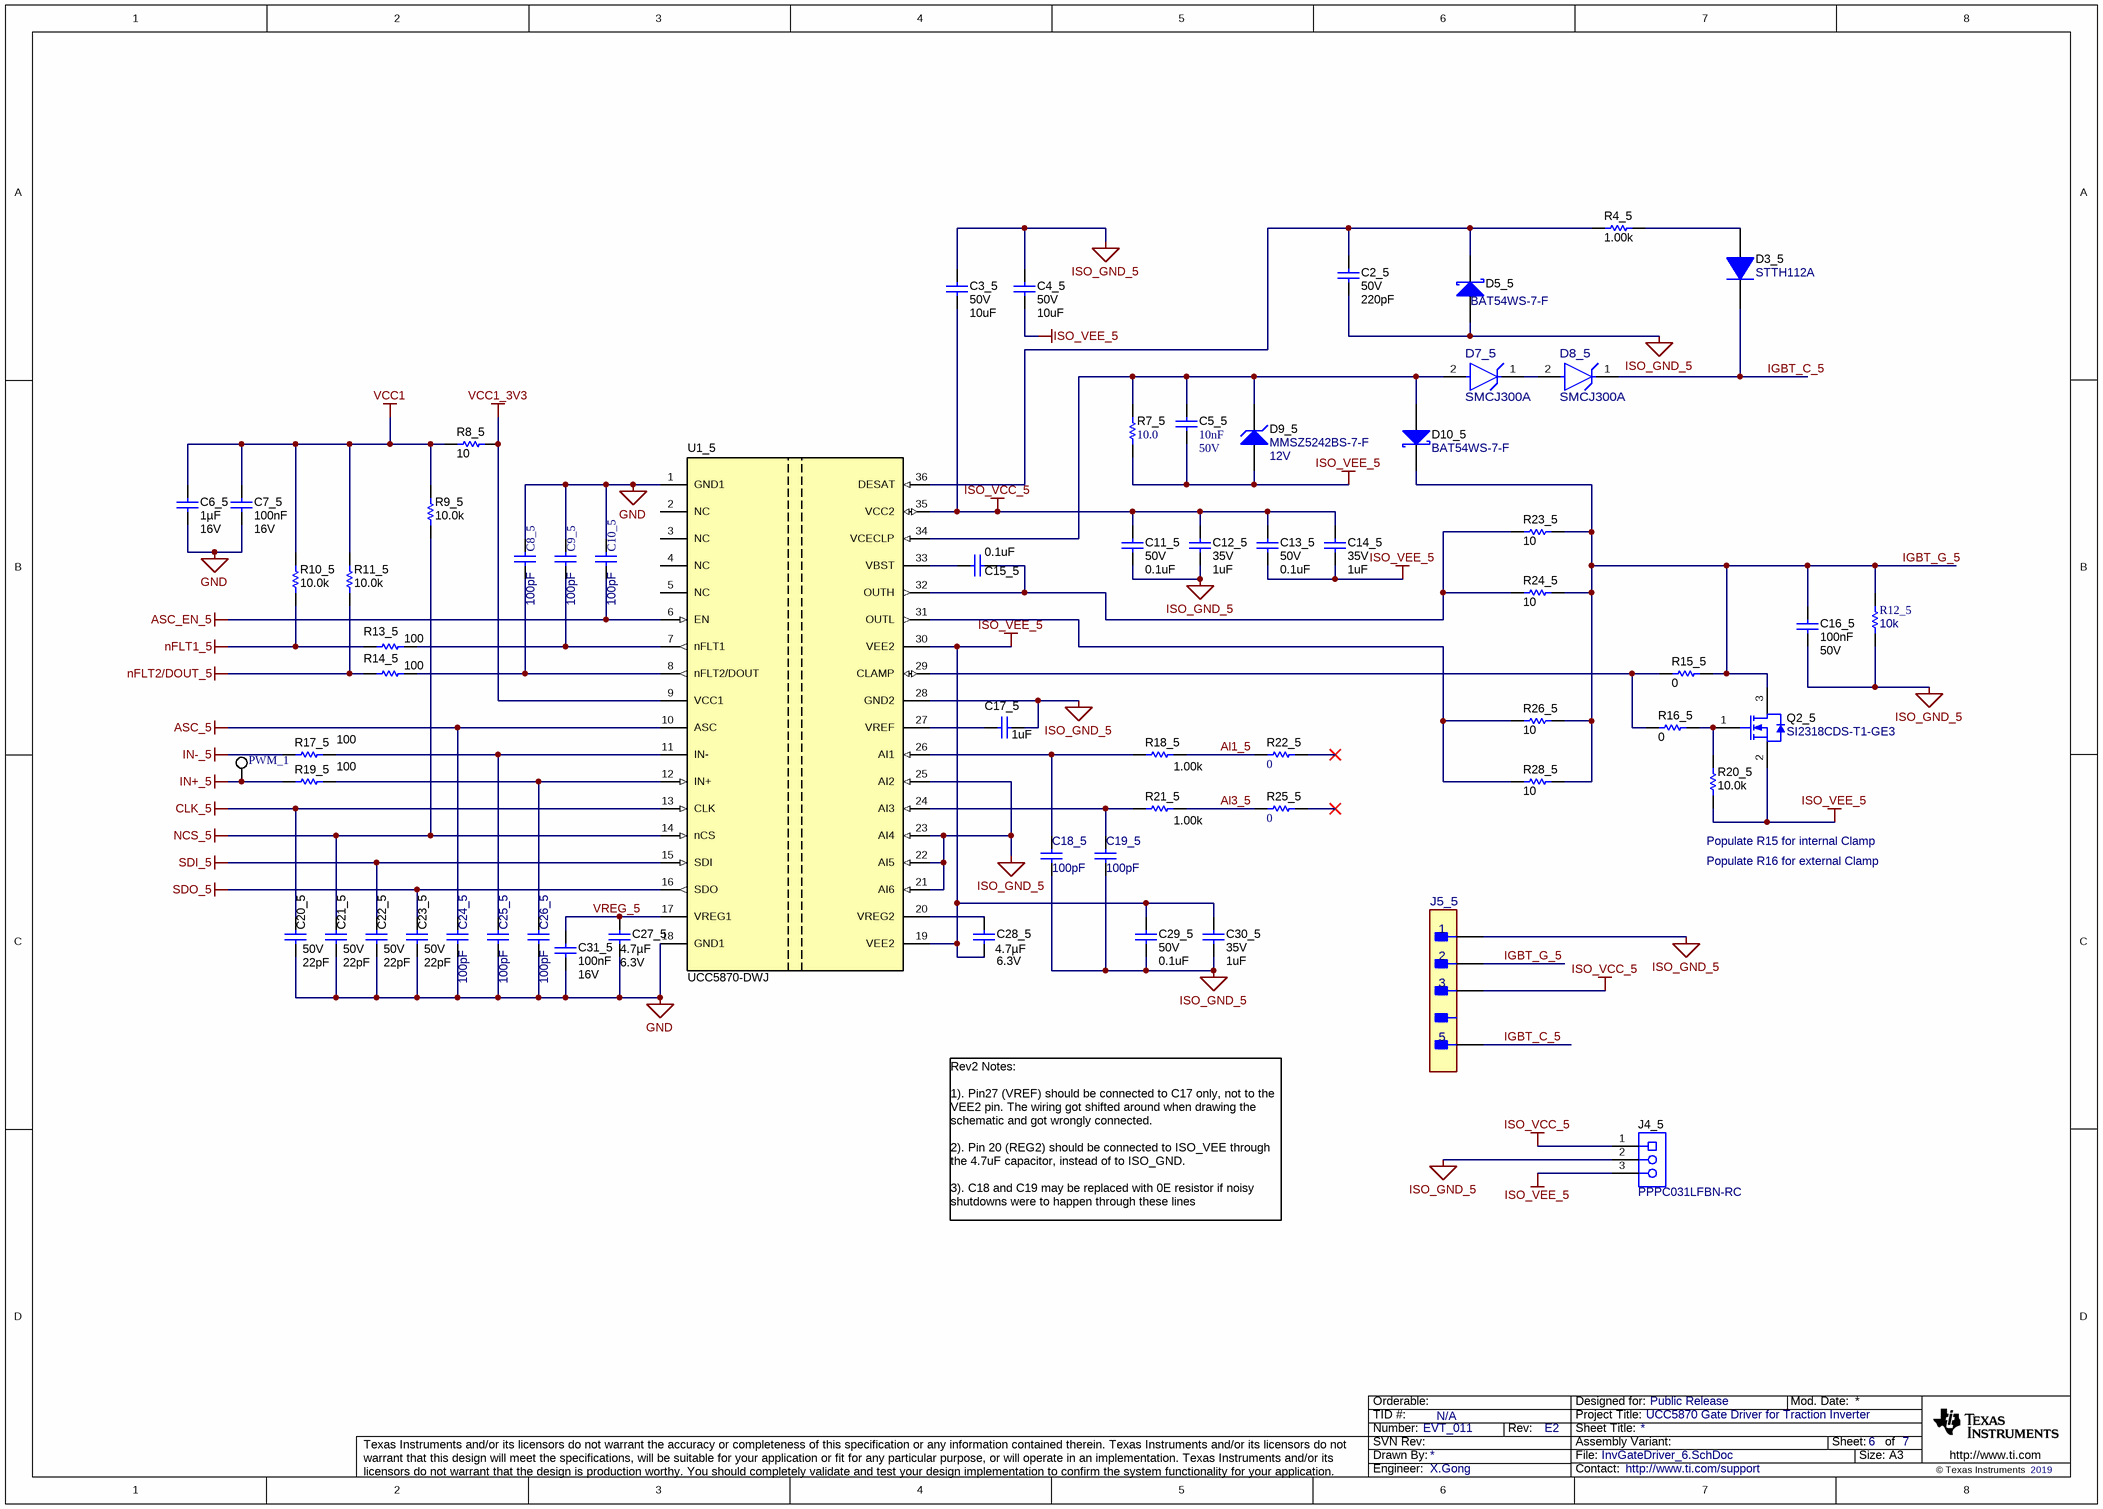
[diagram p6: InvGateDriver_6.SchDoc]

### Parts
C2_5  VDC_V: 50V  ValueDisplayed: 220pF  [0603]  (hidden comment: GRM188R71H221KA01D)
C3_5  VDC_V: 50V  ValueDisplayed: 10uF  [1206_180]  (hidden comment: CL31B106KBHNNNE)
C4_5  VDC_V: 50V  ValueDisplayed: 10uF  [1206_180]  (hidden comment: CL31B106KBHNNNE)
C5_5  Cap_F: 10nF  VDC_V: 50V  [0603]  (hidden comment: GRM188R71H103KA01D)
C6_5  Cap_F: 1µF  VDC_V: 16V  [0603]  (hidden comment: GCM188R71C105MA64D)
C7_5  Cap_F: 100nF  VDC_V: 16V  [0603]  (hidden comment: CGJ3E2X7R1C104K080AA)
C8_5  ValueDisplayed: 100pF  [0603]  (hidden comment: GCM1885C1H101JA16J)
C9_5  ValueDisplayed: 100pF  [0603]  (hidden comment: GCM1885C1H101JA16J)
C10_5  ValueDisplayed: 100pF  [0603]  (hidden comment: GCM1885C1H101JA16J)
C11_5  VDC_V: 50V  ValueDisplayed: 0.1uF  [0603]  (hidden comment: C1608X5R1H104K080AA)
C12_5  VDC_V: 35V  ValueDisplayed: 1uF  [0603]  (hidden comment: CGA3E1X7R1V105K080AC)
C13_5  VDC_V: 50V  ValueDisplayed: 0.1uF  [0603]  (hidden comment: C1608X5R1H104K080AA)
C14_5  VDC_V: 35V  ValueDisplayed: 1uF  [0603]  (hidden comment: CGA3E1X7R1V105K080AC)
C15_5  ValueDisplayed: 0.1uF  [0603]  (hidden comment: C1608X5R1H104K080AA)
C16_5  Cap_F: 100nF  VDC_V: 50V  [0805_HV]  (hidden comment: C0805C104K5RACAUTO)
C17_5  ValueDisplayed: 1uF  [0603]  (hidden comment: CGA3E1X7R1V105K080AC)
C18_5  ValueDisplayed: 100pF  [0603]  (hidden comment: GCM1885C1H101JA16J)
C19_5  ValueDisplayed: 100pF  [0603]  (hidden comment: GCM1885C1H101JA16J)
C20_5  VDC_V: 50V  ValueDisplayed: 22pF  [0603]  (hidden comment: CGA3E2C0G1H220J080AA)
C21_5  VDC_V: 50V  ValueDisplayed: 22pF  [0603]  (hidden comment: CGA3E2C0G1H220J080AA)
C22_5  VDC_V: 50V  ValueDisplayed: 22pF  [0603]  (hidden comment: CGA3E2C0G1H220J080AA)
C23_5  VDC_V: 50V  ValueDisplayed: 22pF  [0603]  (hidden comment: CGA3E2C0G1H220J080AA)
C24_5  ValueDisplayed: 100pF  [0603]  (hidden comment: GCM1885C1H101JA16J)
C25_5  ValueDisplayed: 100pF  [0603]  (hidden comment: GCM1885C1H101JA16J)
C26_5  ValueDisplayed: 100pF  [0603]  (hidden comment: GCM1885C1H101JA16J)
C27_5  Cap_F: 4.7µF  VDC_V: 6.3V  [0603]  (hidden comment: CL10B475KQ8NQND)
C28_5  Cap_F: 4.7µF  VDC_V: 6.3V  [0603]  (hidden comment: CL10B475KQ8NQND)
C29_5  VDC_V: 50V  ValueDisplayed: 0.1uF  [0603]  (hidden comment: C1608X5R1H104K080AA)
C30_5  VDC_V: 35V  ValueDisplayed: 1uF  [0603]  (hidden comment: CGA3E1X7R1V105K080AC)
C31_5  Cap_F: 100nF  VDC_V: 16V  [0603]  (hidden comment: CGJ3E2X7R1C104K080AA)
D3_5  STTH112A  [SMA]
D5_5  BAT54WS-7-F  [SOD-323]
D7_5  SMCJ300A  [FP-SMCJ300A_DO214AB-MFG]
D8_5  SMCJ300A  [FP-SMCJ300A_DO214AB-MFG]
D9_5  MMSZ5242BS-7-F  value 12V  [SOD-323]
D10_5  BAT54WS-7-F  [SOD-323]
J4_5  PPPC031LFBN-RC  [Sullins_PPPC031LFBN-RC]
J5_5  TSW-105-08-G-S-RA-004  [FP-TSW-105-08-G-S-RA-004_HDR4-MFG]  (value not drawn)
PWM_1  5002  [Keystone5002]  (value not drawn)
Q2_5  SI2318CDS-T1-GE3  [SOT-23]
R4_5  ValueDisplayed: 1.00k  [0603]  (hidden comment: CRCW06031K00FKEA)
R7_5  ValueDisplayed: 10.0  [0805_HV]  (hidden comment: CRCW080510R0FKEA)
R8_5  ValueDisplayed: 10  [0805_HV]  (hidden comment: CRCW080510R0JNEA)
R9_5  ValueDisplayed: 10.0k  [0603]  (hidden comment: ERJ-3EKF1002V)
R10_5  ValueDisplayed: 10.0k  [0603]  (hidden comment: ERJ-3EKF1002V)
R11_5  ValueDisplayed: 10.0k  [0603]  (hidden comment: ERJ-3EKF1002V)
R12_5  ValueDisplayed: 10k  [0603]  (hidden comment: CRCW060310K0JNEA)
R13_5  ValueDisplayed: 100  [0603]  (hidden comment: CRCW0603100RJNEA)
R14_5  ValueDisplayed: 100  [0603]  (hidden comment: CRCW0603100RJNEA)
R15_5  ValueDisplayed: 0  [0805_HV]  (hidden comment: CRCW08050000Z0EA)
R16_5  ValueDisplayed: 0  [0805_HV]  (hidden comment: CRCW08050000Z0EA)
R17_5  ValueDisplayed: 100  [0603]  (hidden comment: CRCW0603100RJNEA)
R18_5  ValueDisplayed: 1.00k  [0603]  (hidden comment: CRCW06031K00FKEA)
R19_5  ValueDisplayed: 100  [0603]  (hidden comment: CRCW0603100RJNEA)
R20_5  ValueDisplayed: 10.0k  [0603]  (hidden comment: RCG060310K0FKEA)
R21_5  ValueDisplayed: 1.00k  [0603]  (hidden comment: CRCW06031K00FKEA)
R22_5  ValueDisplayed: 0  [0603]  (hidden comment: CRCW06030000Z0EA)
R23_5  ValueDisplayed: 10  [2010]  (hidden comment: CRCW201010R0JNEF)
R24_5  ValueDisplayed: 10  [2010]  (hidden comment: CRCW201010R0JNEF)
R25_5  ValueDisplayed: 0  [0603]  (hidden comment: CRCW06030000Z0EA)
R26_5  ValueDisplayed: 10  [2010]  (hidden comment: CRCW201010R0JNEF)
R28_5  ValueDisplayed: 10  [2010]  (hidden comment: CRCW201010R0JNEF)
U1_5  UCC5870-DWJ  [DWJ0036A]

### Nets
ASC_5: C24_5.1 U1_5.10(ASC)  [project net ASC_1]
ASC_EN_5: C10_5.2 U1_5.6(EN)  [project net ASC_EN]
CLK_5: C20_5.1 U1_5.13(CLK)  [project net CLK]
GND: C6_5.2 C7_5.2 C8_5.1 C9_5.1 C10_5.1 C20_5.2 C21_5.2 C22_5.2 C23_5.2 C24_5.2 C25_5.2 C26_5.2 C27_5.2 C31_5.2 U1_5.1(GND1) U1_5.18(GND1)
IN+_5: PWM_1.1 R19_5.1  [project net IN+_A]
IN-_5: R17_5.1  [project net IN-_A]
ISO_GND_5: C2_5.1 C3_5.1 C4_5.1 C11_5.2 C12_5.2 C16_5.2 C17_5.2 C18_5.2 C19_5.2 C29_5.2 C30_5.1 D5_5.2(A) J4_5.2 J5_5.1 R12_5.1 U1_5.21(AI6) U1_5.22(AI5) U1_5.23(AI4) U1_5.25(AI2) U1_5.28(GND2)
ISO_VCC_5: C3_5.2 C11_5.1 C12_5.1 C13_5.1 C14_5.1 J4_5.1 J5_5.3 U1_5.35(VCC2)
ISO_VEE_5: C4_5.2 C5_5.2 C13_5.2 C14_5.2 C28_5.2 C29_5.1 C30_5.2 D9_5.2(A) J4_5.3 Q2_5.2(S) R7_5.1 R20_5.1 U1_5.19(VEE2) U1_5.30(VEE2)
NCS_5: C21_5.1 R9_5.1 U1_5.14(nCS)  [project net NCS]
nFLT1_5: R10_5.2 R13_5.1  [project net nFLT1_1]
nFLT2/DOUT_5: R11_5.1 R14_5.1  [project net nFLT2/DOUT_1]
SDI_5: C22_5.1 U1_5.15(SDI)  [project net SDI]
SDO_5: C23_5.1 U1_5.16(SDO)  [project net SDO]
VCC1: C6_5.1 C7_5.1 R8_5.1 R9_5.2 R10_5.1 R11_5.2
VCC1_3V3: R8_5.2 U1_5.9(VCC1)
Al1_5: R18_5.2 R22_5.1
Al3_5: R21_5.2 R25_5.1
IGBT_C_5: D3_5.1(K) D8_5.1(CATHODE) J5_5.5
IGBT_G_5: C16_5.1 D10_5.1(K) J5_5.2 Q2_5.3(D) R12_5.2 R15_5.1 R23_5.2 R24_5.2 R26_5.2 R28_5.2
VREG_5: C27_5.1 C31_5.1 U1_5.17(VREG1)
NetC2_5_2: C2_5.2 D5_5.1(K) R4_5.1 U1_5.36(DESAT)
NetC5_5_1: C5_5.1 D7_5.2(ANODE) D9_5.1(K) D10_5.2(A) R7_5.2 U1_5.34(VCECLP)
NetC8_5_2: C8_5.2 R14_5.2 U1_5.8(nFLT2/DOUT)
NetC9_5_2: C9_5.2 R13_5.2 U1_5.7(nFLT1)
NetC15_5_1: C15_5.1 U1_5.33(VBST)
NetC15_5_2: C15_5.2 R23_5.1 R24_5.1 U1_5.32(OUTH)
NetC17_5_1: C17_5.1 U1_5.27(VREF)
NetC18_5_1: C18_5.1 R18_5.1 U1_5.26(AI1)
NetC19_5_1: C19_5.1 R21_5.1 U1_5.24(AI3)
NetC25_5_1: C25_5.1 R17_5.2 U1_5.11(IN-)
NetC26_5_1: C26_5.1 R19_5.2 U1_5.12(IN+)
NetC28_5_1: C28_5.1 U1_5.20(VREG2)
NetD3_5_2: D3_5.2(A) R4_5.2
NetD7_5_1: D7_5.1(CATHODE) D8_5.2(ANODE)
NetQ2_5_1: Q2_5.1(G) R16_5.1 R20_5.2
NetR15_5_2: R15_5.2 R16_5.2 U1_5.29(CLAMP)
NetR26_5_1: R26_5.1 R28_5.1 U1_5.31(OUTL)

Not connected (* = marked no-connect by the designer): R22_5 2*; R25_5 2*; U1_5 2(NC) 3(NC) 4(NC) 5(NC)

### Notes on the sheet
- (near R20_5) Populate R15 for internal Clamp
- Populate R16 for external Clamp
- Rev2 Notes:
  1). Pin27 (VREF) should be connected to C17 only, not to the VEE2 pin. The wiring got shifted around when drawing the schematic and got wrongly connected.
  2). Pin 20 (REG2) should be connected to ISO_VEE through the 4.7uF capacitor, instead of to ISO_GND.
  3). C18 and C19 may be replaced with 0E resistor if noisy shutdowns were to happen through these lines

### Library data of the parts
C2_5 = CMP-0007442-5: as C2_3 on sheet InvGateDriver_4
C3_5 = CMP-0008802-2: as C3_3 on sheet InvGateDriver_4
C4_5 = CMP-0008802-2: as C4_3 on sheet InvGateDriver_4
C5_5 = CMP-0007433-4: as C5_3 on sheet InvGateDriver_4
C6_5 = CMP-0007137-5: as C6_3 on sheet InvGateDriver_4
C7_5 = CMP-0007106-4: as C7_3 on sheet InvGateDriver_4
C8_5 C9_5 C10_5 C18_5 C19_5 C24_5 C25_5 C26_5 = CMP-0750041-1: as C8_3 on sheet InvGateDriver_4
C11_5 C29_5 = CMP-0007010-5: as C11_3 on sheet InvGateDriver_4
C12_5 C14_5 C30_5 = CMP-0007067-4: as C12_3 on sheet InvGateDriver_4
C13_5 = CMP-0007010-5: as C13_3 on sheet InvGateDriver_4
C15_5 = CMP-0007010-5: as C15_3 on sheet InvGateDriver_4
C16_5 = CMP-0007725-2: as C16_3 on sheet InvGateDriver_4
C17_5 = CMP-0007067-4: as C17_3 on sheet InvGateDriver_4
C20_5 C21_5 C22_5 C23_5 = CMP-0007071-3: as C20_3 on sheet InvGateDriver_4
C27_5 C28_5 = CMP-0007112-4: as C27_3 on sheet InvGateDriver_4
C31_5 = CMP-0007106-4: as C31_3 on sheet InvGateDriver_4
D3_5 = CMP-0077081-2: as D3_3 on sheet InvGateDriver_4
D5_5 D10_5 = CMP-0028458-2: as D5_3 on sheet InvGateDriver_4
D7_5 D8_5 = CMP-0088475-1: as D7_3 on sheet InvGateDriver_4
D9_5 = CMP-0005831-4: as D9_3 on sheet InvGateDriver_4
J4_5 = CMP-0054646-1: as J4_3 on sheet InvGateDriver_4
J5_5 = CMP-0088430-1: as J5_3 on sheet InvGateDriver_4
PWM_1 = CMP-0055139-1: as PWM_3 on sheet InvGateDriver_4
Q2_5 = CMP-0000739-1: as Q2_3 on sheet InvGateDriver_4
R4_5 R18_5 R21_5 = CMP-0022109-5: as R4_3 on sheet InvGateDriver_4
R7_5 = CMP-0020847-3: as R7_3 on sheet InvGateDriver_4
R8_5 = CRCW080510R0JNEA: as R8_3 on sheet InvGateDriver_4
R9_5 R10_5 R11_5 = CMP-0022684-3: as R9_3 on sheet InvGateDriver_4
R12_5 = CMP-0025701-4: as R12_3 on sheet InvGateDriver_4
R13_5 R14_5 R17_5 R19_5 = CMP-0025700-4: as R13_3 on sheet InvGateDriver_4
R15_5 R16_5 = CRCW08050000Z0EA: as R15_3 on sheet InvGateDriver_4
R20_5 = RCG060310K0FKEA: as R20_3 on sheet InvGateDriver_4
R22_5 R25_5 = CMP-0025697-4: as R22_3 on sheet InvGateDriver_4
R23_5 R24_5 R26_5 R28_5 = CRCW201010R0JNEF: as R23_3 on sheet InvGateDriver_4
U1_5 = CMP-0080759-3: as U1_3 on sheet InvGateDriver_4

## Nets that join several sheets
ASC: Hardware and Connector_r1 (J1.7), InvGateDriver_1 (C24.1 U1.10), InvGateDriver_3 (C24_2.1 U1_2.10), InvGateDriver_5 (C24_4.1 U1_4.10)
ASC_1: Hardware and Connector_r1 (J1.4), InvGateDriver_2 (C24_1.1 U1_1.10), InvGateDriver_4 (C24_3.1 U1_3.10), InvGateDriver_6 (C24_5.1 U1_5.10)
ASC_EN: Hardware and Connector_r1 (J1.5 R2.2), InvGateDriver_1 (C10.2 U1.6), InvGateDriver_2 (C10_1.2 U1_1.6), InvGateDriver_3 (C10_2.2 U1_2.6), InvGateDriver_4 (C10_3.2 U1_3.6), InvGateDriver_5 (C10_4.2 U1_4.6), InvGateDriver_6 (C10_5.2 U1_5.6)
CLK: Hardware and Connector_r1 (J1.20), InvGateDriver_1 (C20.1 U1.13), InvGateDriver_2 (C20_1.1 U1_1.13), InvGateDriver_3 (C20_2.1 U1_2.13), InvGateDriver_4 (C20_3.1 U1_3.13), InvGateDriver_5 (C20_4.1 U1_4.13), InvGateDriver_6 (C20_5.1 U1_5.13)
GND: Hardware and Connector_r1 (7 pins), InvGateDriver_1 (16 pins), InvGateDriver_2 (16 pins), InvGateDriver_3 (16 pins), InvGateDriver_4 (16 pins), InvGateDriver_5 (16 pins), InvGateDriver_6 (16 pins)
IN+_A: Hardware and Connector_r1 (J1.15), InvGateDriver_5 (R17_4.1), InvGateDriver_6 (PWM_1.1 R19_5.1)
IN+_B: Hardware and Connector_r1 (J1.14), InvGateDriver_3 (R17_2.1), InvGateDriver_4 (PWM_3.1 R19_3.1)
IN+_C: Hardware and Connector_r1 (J1.16), InvGateDriver_1 (R17.1), InvGateDriver_2 (PWM_5.1 R19_1.1)
IN-_A: Hardware and Connector_r1 (J1.13), InvGateDriver_5 (PWM_2.1 R19_4.1), InvGateDriver_6 (R17_5.1)
IN-_B: Hardware and Connector_r1 (J1.18), InvGateDriver_3 (PWM_4.1 R19_2.1), InvGateDriver_4 (R17_3.1)
IN-_C: Hardware and Connector_r1 (J1.17), InvGateDriver_1 (PWM_6.1 R19.1), InvGateDriver_2 (R17_1.1)
NCS: Hardware and Connector_r1 (J1.24), InvGateDriver_1 (C21.1 R9.1 U1.14), InvGateDriver_2 (C21_1.1 R9_1.1 U1_1.14), InvGateDriver_3 (C21_2.1 R9_2.1 U1_2.14), InvGateDriver_4 (C21_3.1 R9_3.1 U1_3.14), InvGateDriver_5 (C21_4.1 R9_4.1 U1_4.14), InvGateDriver_6 (C21_5.1 R9_5.1 U1_5.14)
nFLT1: Hardware and Connector_r1 (J1.11 R1.1), InvGateDriver_1 (R10.2 R13.1), InvGateDriver_3 (R10_2.2 R13_2.1), InvGateDriver_5 (R10_4.2 R13_4.1)
nFLT1_1: Hardware and Connector_r1 (J1.8 R29.1), InvGateDriver_2 (R10_1.2 R13_1.1), InvGateDriver_4 (R10_3.2 R13_3.1), InvGateDriver_6 (R10_5.2 R13_5.1)
nFLT2/DOUT: Hardware and Connector_r1 (J1.10), InvGateDriver_1 (R11.1 R14.1), InvGateDriver_3 (R11_2.1 R14_2.1), InvGateDriver_5 (R11_4.1 R14_4.1)
nFLT2/DOUT_1: Hardware and Connector_r1 (J1.2), InvGateDriver_2 (R11_1.1 R14_1.1), InvGateDriver_4 (R11_3.1 R14_3.1), InvGateDriver_6 (R11_5.1 R14_5.1)
SDI: Hardware and Connector_r1 (J1.21), InvGateDriver_1 (C22.1 U1.15), InvGateDriver_2 (C22_1.1 U1_1.15), InvGateDriver_3 (C22_2.1 U1_2.15), InvGateDriver_4 (C22_3.1 U1_3.15), InvGateDriver_5 (C22_4.1 U1_4.15), InvGateDriver_6 (C22_5.1 U1_5.15)
SDO: Hardware and Connector_r1 (J1.19), InvGateDriver_1 (C23.1 U1.16), InvGateDriver_2 (C23_1.1 U1_1.16), InvGateDriver_3 (C23_2.1 U1_2.16), InvGateDriver_4 (C23_3.1 U1_3.16), InvGateDriver_5 (C23_4.1 U1_4.16), InvGateDriver_6 (C23_5.1 U1_5.16)
VCC1: Hardware and Connector_r1 (6 pins), InvGateDriver_1 (6 pins), InvGateDriver_2 (6 pins), InvGateDriver_3 (6 pins), InvGateDriver_4 (6 pins), InvGateDriver_5 (6 pins), InvGateDriver_6 (6 pins)
VCC1_3V3: InvGateDriver_1 (R8.2 U1.9), InvGateDriver_2 (R8_1.2 U1_1.9), InvGateDriver_3 (R8_2.2 U1_2.9), InvGateDriver_4 (R8_3.2 U1_3.9), InvGateDriver_5 (R8_4.2 U1_4.9), InvGateDriver_6 (R8_5.2 U1_5.9)

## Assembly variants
001: not fitted C16 C16_1 C16_2 C16_3 C16_4 C16_5 FID1 FID2 FID3 Q2 Q2_1 Q2_2 Q2_3 Q2_4 Q2_5 R16 R16_1 R16_2 R16_3 R16_4 R16_5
